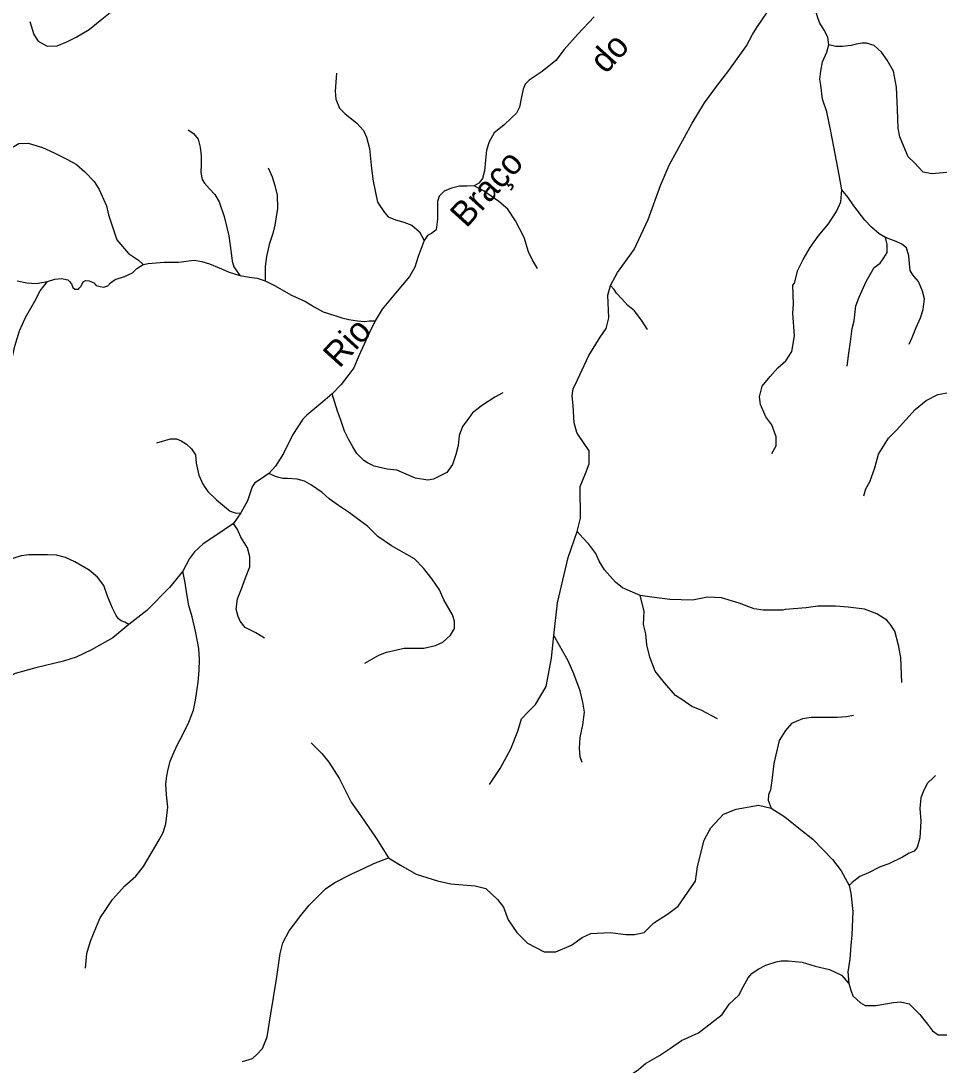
# Model space of a CAD drawing. Extents: x 436.3 to 500.4, y 8231 to 8286.4.
# Drawn here: x 466.93 to 474.29, y 8238.26 to 8246.62 of the extents above; entities that cross this region are included whole.
import ezdxf
from ezdxf.enums import TextEntityAlignment as Align

# ---------------------------------------------------------------- set-up
doc = ezdxf.new("R2010")
doc.units = 0
doc.header["$LTSCALE"] = 0.08
doc.linetypes.add('LONG_DASHED', pattern=[7.5, 6, -1.5])
doc.layers.add('61', color=7, linetype='Continuous')
doc.layers.add('9', color=7, linetype='LONG_DASHED', lineweight=25)

msp = doc.modelspace()

# ---------------------------------------------------------------- linework, layer by layer
at = {"layer": '9'}
for points in [[(467.005, 8246.619), (467.0356, 8246.5158), (467.07, 8246.4624), (467.1428, 8246.4206), (467.2232, 8246.4246), (467.2997, 8246.4554), (467.3763, 8246.4937), (467.4796, 8246.555), (467.5677, 8246.6279), (467.7016, 8246.7351), (467.7628, 8246.8079), (467.8088, 8246.8577), (467.8776, 8246.8999), (467.9656, 8246.9535), (468.0422, 8247.0339), (468.0843, 8247.1105), (468.1074, 8247.1845), (468.1226, 8247.303), (468.115, 8247.4025), (468.0614, 8247.5517), (468.0308, 8247.6435), (468.0039, 8247.7047)], [(471.6561, 8244.5046), (471.7121, 8244.6097), (471.845, 8244.7919), (471.958, 8245.0334), (472.0559, 8245.3065), (472.1259, 8245.4676), (472.3081, 8245.8037), (472.4074, 8245.9685), (472.5125, 8246.1086), (472.6036, 8246.2275), (472.7438, 8246.4237), (472.7929, 8246.5147), (472.828, 8246.5707), (472.9122, 8246.6969), (472.9684, 8246.7739), (473.0035, 8246.858), (473.0315, 8246.9701), (473.0528, 8247.1661)], [(473.404, 8246.4319), (473.3955, 8246.4933), (473.3672, 8246.5503), (473.3531, 8246.5713), (473.3322, 8246.6063), (473.3181, 8246.6412), (473.3042, 8246.6833), (473.2902, 8246.7603), (473.2833, 8246.8372), (473.2693, 8246.9073), (473.2273, 8246.9912), (473.1772, 8247.0397), (473.1165, 8247.0893), (473.0528, 8247.1661)], [(471.5237, 8246.6564), (471.3932, 8246.5179), (471.2831, 8246.3957), (471.2179, 8246.3061), (471.1067, 8246.2186), (471.0048, 8246.1493), (470.9722, 8246.1167), (470.9559, 8246.076), (470.9436, 8246.0149), (470.9274, 8245.9334), (470.903, 8245.8845), (470.8622, 8245.8478), (470.8002, 8245.7888), (470.7227, 8245.7277), (470.6821, 8245.6544), (470.6616, 8245.5892), (470.6536, 8245.5078), (470.6454, 8245.4222), (470.6292, 8245.361), (470.6007, 8245.3244), (470.564, 8245.304)], [(473.507, 8245.2707), (473.4858, 8245.3911), (473.4439, 8245.6151), (473.416, 8245.755), (473.3881, 8245.895), (473.3531, 8245.9963), (473.3392, 8246.1083), (473.3321, 8246.1573), (473.3393, 8246.2204), (473.3533, 8246.2974), (473.3884, 8246.3744), (473.404, 8246.4319)], [(474.3704, 8245.412), (474.3199, 8245.4073), (474.2283, 8245.398), (474.1595, 8245.4117), (474.0863, 8245.4894), (474.0405, 8245.5351), (474.0039, 8245.6174), (473.9719, 8245.6952), (473.9582, 8245.7638), (473.9537, 8245.9147), (473.9447, 8246.0932), (473.922, 8246.2212), (473.8714, 8246.309), (473.8256, 8246.3729), (473.7661, 8246.4278), (473.7064, 8246.446), (473.6698, 8246.4459), (473.624, 8246.4368), (473.5827, 8246.4276), (473.514, 8246.4183), (473.4589, 8246.4182), (473.404, 8246.4319)], [(469.4616, 8246.2048), (469.4496, 8246.0616), (469.4556, 8245.996), (469.4854, 8245.9244), (469.5272, 8245.8827), (469.6228, 8245.8051), (469.6766, 8245.7454), (469.7004, 8245.6917), (469.7243, 8245.6023), (469.7422, 8245.4411), (469.7542, 8245.3397), (469.7901, 8245.1726), (469.8438, 8245.089), (469.8737, 8245.0532), (469.9334, 8245.0292), (469.999, 8245.0112), (470.0648, 8244.9873), (470.1244, 8244.9335), (470.163, 8244.8648)], [(468.2731, 8245.7512), (468.3149, 8245.7219), (468.3525, 8245.6761), (468.3692, 8245.6134), (468.3776, 8245.5424), (468.3776, 8245.4757), (468.3734, 8245.4089), (468.386, 8245.3545), (468.4028, 8245.3253), (468.4445, 8245.2794), (468.4863, 8245.2334), (468.5199, 8245.175), (468.5617, 8245.058), (468.5994, 8244.9034), (468.6161, 8244.7654), (468.6245, 8244.6986), (468.6371, 8244.6525), (468.6871, 8244.5846)], [(466.6711, 8245.6228), (466.6978, 8245.6051), (466.7378, 8245.5786), (466.7511, 8245.5787), (466.8045, 8245.5832), (466.8223, 8245.5921), (466.8755, 8245.6188), (466.9155, 8245.6412), (466.9912, 8245.6457), (467.1067, 8245.6106), (467.2, 8245.5664), (467.3066, 8245.5134), (467.3777, 8245.4737), (467.4443, 8245.4162), (467.5199, 8245.3365), (467.5599, 8245.2745), (467.6177, 8245.1415), (467.6354, 8245.0704), (467.7021, 8244.8709), (467.7954, 8244.7601), (467.8754, 8244.7069), (467.911, 8244.6715)], [(468.913, 8245.4465), (468.9464, 8245.3754), (468.9673, 8245.3044), (468.9841, 8245.2291), (468.9883, 8245.1205), (468.9674, 8244.9868), (468.9507, 8244.9199), (468.9215, 8244.8322), (468.9006, 8244.736), (468.888, 8244.6565), (468.888, 8244.6189), (468.8903, 8244.5409)], [(470.564, 8245.304), (470.5069, 8245.3), (470.4458, 8245.3), (470.3805, 8245.2838), (470.3235, 8245.2594), (470.2827, 8245.2187), (470.2706, 8245.178), (470.2706, 8245.0353), (470.2584, 8244.9497), (470.2218, 8244.9212), (470.1892, 8244.905), (470.163, 8244.8648)], [(471.0714, 8244.6399), (471.0301, 8244.7071), (470.999, 8244.7743), (470.9628, 8244.888), (470.8956, 8245.0224), (470.8337, 8245.1153), (470.7613, 8245.1774), (470.6735, 8245.2394), (470.6425, 8245.26), (470.564, 8245.304)], [(472.9477, 8243.1575), (472.9826, 8243.2207), (472.9825, 8243.2909), (472.9474, 8243.3891), (472.8984, 8243.4523), (472.8562, 8243.5504), (472.8492, 8243.6136), (472.8701, 8243.6978), (472.9331, 8243.775), (472.996, 8243.8452), (473.059, 8243.9014), (473.1078, 8243.9754), (473.1288, 8244.1016), (473.1146, 8244.2839), (473.1216, 8244.354), (473.1145, 8244.5082), (473.1286, 8244.5222), (473.1565, 8244.6274), (473.1985, 8244.7115), (473.2546, 8244.8096), (473.3176, 8244.9008), (473.4017, 8244.9989), (473.4648, 8245.097), (473.4998, 8245.1741), (473.507, 8245.2707)], [(473.8591, 8244.888), (473.8073, 8244.919), (473.7452, 8244.9706), (473.6934, 8245.0275), (473.6054, 8245.1414), (473.5587, 8245.2086), (473.507, 8245.2707)], [(473.5499, 8243.8569), (473.5639, 8243.9621), (473.5778, 8244.0533), (473.5918, 8244.1585), (473.6057, 8244.2216), (473.6197, 8244.3408), (473.6477, 8244.4109), (473.7037, 8244.5371), (473.7668, 8244.6493), (473.8158, 8244.6844), (473.8439, 8244.7265), (473.8719, 8244.7686), (473.872, 8244.8315), (473.8591, 8244.888)], [(474.0479, 8244.0331), (474.0702, 8244.0889), (474.1037, 8244.1672), (474.1372, 8244.2454), (474.1595, 8244.3125), (474.1699, 8244.3962), (474.1544, 8244.4584), (474.1233, 8244.5361), (474.0871, 8244.5775), (474.0715, 8244.5982), (474.0559, 8244.624), (474.0508, 8244.681), (474.0456, 8244.7431), (474.0249, 8244.8053), (473.9887, 8244.8363), (473.9421, 8244.857), (473.8591, 8244.888)], [(470.163, 8244.8648), (470.1151, 8244.7368), (470.0884, 8244.6515), (470.0457, 8244.5768), (469.9338, 8244.4435), (469.8273, 8244.3156), (469.7708, 8244.2202)], [(467.911, 8244.6715), (467.9521, 8244.6793), (468.0791, 8244.6903), (468.1952, 8244.6903), (468.3205, 8244.708), (468.3822, 8244.6971), (468.4439, 8244.6791), (468.5201, 8244.6464), (468.6, 8244.6101), (468.6871, 8244.5846)], [(467.1461, 8244.5357), (467.2041, 8244.554), (467.2586, 8244.5614), (467.3094, 8244.5507), (467.3203, 8244.5398), (467.3384, 8244.5181), (467.3493, 8244.4891), (467.3639, 8244.4746), (467.3929, 8244.4747), (467.4002, 8244.4819), (467.4146, 8244.5001), (467.4328, 8244.5328), (467.4513, 8244.5443), (467.4803, 8244.5408), (467.5167, 8244.5264), (467.5348, 8244.5047), (467.5674, 8244.4974), (467.5966, 8244.4902), (467.6292, 8244.5012), (467.6509, 8244.5266), (467.6872, 8244.552), (467.7634, 8244.5775), (467.8265, 8244.6047), (467.8622, 8244.6403), (467.911, 8244.6715)], [(466.903, 8244.5423), (466.9792, 8244.5244), (467.0554, 8244.521), (467.1461, 8244.5357)], [(468.6871, 8244.5846), (468.7633, 8244.57), (468.8249, 8244.5628), (468.8903, 8244.5409)], [(468.8903, 8244.5409), (468.9629, 8244.5045), (469.1008, 8244.4281), (469.2133, 8244.3772), (469.2823, 8244.3335), (469.3549, 8244.2935), (469.4477, 8244.2643), (469.5022, 8244.246), (469.5603, 8244.2314), (469.6292, 8244.2204), (469.6873, 8244.2166), (469.7236, 8244.2203), (469.7708, 8244.2202)], [(466.5022, 8243.1071), (466.5447, 8243.1924), (466.6031, 8243.3045), (466.7467, 8243.5607), (466.7999, 8243.6513), (466.837, 8243.7792), (466.8582, 8243.8964), (466.8848, 8244.0189), (466.922, 8244.1414), (466.9699, 8244.2479), (467.0448, 8244.3776), (467.0873, 8244.4628), (467.1461, 8244.5357)], [(471.3892, 8242.533), (471.4138, 8242.6402), (471.4134, 8242.8931), (471.4553, 8242.9984), (471.4832, 8243.0756), (471.4831, 8243.181), (471.3983, 8243.3053), (471.3843, 8243.3264), (471.3632, 8243.4037), (471.356, 8243.544), (471.349, 8243.6212), (471.3559, 8243.6773), (471.3908, 8243.7474), (471.4816, 8243.9438), (471.5725, 8244.091), (471.6215, 8244.1611), (471.6424, 8244.2452), (471.6352, 8244.4275), (471.6561, 8244.5046)], [(471.9526, 8244.1517), (471.9077, 8244.2177), (471.8469, 8244.3023), (471.7941, 8244.3446), (471.7466, 8244.3974), (471.7044, 8244.4423), (471.6859, 8244.4714), (471.6561, 8244.5046)], [(469.7708, 8244.2202), (469.7259, 8244.1288), (469.6408, 8243.9419), (469.5982, 8243.8458), (469.5503, 8243.7817), (469.497, 8243.7124), (469.4258, 8243.635)], [(469.4258, 8243.635), (469.3512, 8243.571), (469.2232, 8243.4642), (469.1912, 8243.4322), (469.1114, 8243.3092), (469.0368, 8243.1595), (468.9728, 8243.0579), (468.9196, 8242.9991)], [(470.7926, 8243.6454), (470.7298, 8243.6094), (470.6311, 8243.5466), (470.5504, 8243.4837), (470.5056, 8243.4207), (470.4697, 8243.3758), (470.4429, 8243.3038), (470.434, 8243.2227), (470.4161, 8243.1507), (470.3893, 8243.0697), (470.3445, 8243.0067), (470.2368, 8242.9528), (470.1919, 8242.9439), (470.0946, 8242.9611), (470.0196, 8242.9925), (469.9445, 8243.024), (469.8664, 8243.0336), (469.7632, 8243.0557), (469.71, 8243.084), (469.6787, 8243.1028), (469.6224, 8243.1594), (469.5911, 8243.2127), (469.5566, 8243.2723), (469.5253, 8243.3382), (469.494, 8243.4323), (469.4689, 8243.4981), (469.4258, 8243.635)], [(473.6842, 8242.8196), (473.7, 8242.8752), (473.7316, 8242.9309), (473.7711, 8243.0423), (473.8027, 8243.1536), (473.8818, 8243.2808), (473.9452, 8243.3445), (474.0957, 8243.5115), (474.1829, 8243.5832), (474.278, 8243.631), (474.3652, 8243.647), (474.4445, 8243.6631), (474.5476, 8243.6552), (474.6825, 8243.592), (474.8095, 8243.5127), (474.9127, 8243.4731), (474.9762, 8243.4653), (475.1031, 8243.4892), (475.2301, 8243.5291), (475.3253, 8243.5769), (475.418, 8243.6362)], [(468.0221, 8243.2445), (468.1305, 8243.2771), (468.1792, 8243.2771), (468.2172, 8243.2609), (468.2605, 8243.2336), (468.2984, 8243.1956), (468.331, 8243.1467), (468.3365, 8243.0815), (468.3582, 8242.9837), (468.3908, 8242.913), (468.4288, 8242.8531), (468.4993, 8242.7878), (468.5644, 8242.7334), (468.6078, 8242.6953), (468.6566, 8242.679), (468.6941, 8242.6824)], [(468.9196, 8242.9991), (468.8502, 8242.951), (468.8077, 8242.9243), (468.7863, 8242.8921), (468.7486, 8242.7785), (468.6941, 8242.6824), (468.6349, 8242.5974)], [(469.6885, 8241.4784), (469.7984, 8241.5413), (469.8611, 8241.5675), (470.0025, 8241.5988), (470.1595, 8241.5985), (470.2537, 8241.6195), (470.3112, 8241.6456), (470.374, 8241.7034), (470.4054, 8241.7559), (470.4053, 8241.8137), (470.3896, 8241.8662), (470.3213, 8241.9872), (470.2845, 8242.0661), (470.2269, 8242.1503), (470.1587, 8242.2397), (470.0853, 8242.3133), (469.902, 8242.4188), (469.7919, 8242.4924), (469.7081, 8242.5766), (469.6504, 8242.6187), (469.565, 8242.6836), (469.4759, 8242.7416), (469.4025, 8242.7942), (469.3449, 8242.8468), (469.261, 8242.9047), (469.2034, 8242.9363), (469.1459, 8242.9521), (469.0673, 8242.9575), (469.0307, 8242.9576), (468.9888, 8242.9681), (468.9731, 8242.9734), (468.9196, 8242.9991)], [(468.6349, 8242.5974), (468.4874, 8242.4948), (468.3915, 8242.4359), (468.3222, 8242.3717), (468.284, 8242.316), (468.2307, 8242.2143)], [(468.8852, 8241.6781), (468.8147, 8241.7216), (468.7279, 8241.7652), (468.69, 8241.8142), (468.6736, 8241.8523), (468.6574, 8241.9121), (468.6681, 8241.9937), (468.7005, 8242.0752), (468.733, 8242.1623), (468.7653, 8242.2493), (468.7652, 8242.3308), (468.749, 8242.4016), (468.6947, 8242.4886), (468.6675, 8242.5485), (468.6349, 8242.5974)], [(471.2014, 8241.6994), (471.2311, 8241.9611), (471.3163, 8242.3241), (471.3892, 8242.533)], [(471.894, 8242.0206), (471.7508, 8242.0831), (471.6946, 8242.1269), (471.6074, 8242.2268), (471.5637, 8242.2955), (471.5388, 8242.358), (471.4826, 8242.433), (471.4327, 8242.4829), (471.3892, 8242.533)], [(467.0567, 8242.3465), (466.9967, 8242.3465), (466.9358, 8242.3392), (466.8757, 8242.3199), (466.8181, 8242.3), (466.7939, 8242.2858), (466.7715, 8242.2723), (466.7485, 8242.2603)], [(467.7973, 8241.7891), (467.7649, 8241.8083), (467.7349, 8241.8169), (467.7133, 8241.8341), (467.6961, 8241.86), (467.6659, 8241.9204), (467.6271, 8242.0154), (467.5969, 8242.1017), (467.5452, 8242.1664), (467.4807, 8242.2225), (467.3645, 8242.2915), (467.2913, 8242.3259), (467.2182, 8242.343), (467.1451, 8242.3472), (467.0677, 8242.3471), (467.0567, 8242.3465)], [(467.4504, 8239.0358), (467.4602, 8239.1537), (467.4896, 8239.252), (467.5386, 8239.3699), (467.5681, 8239.4386), (467.6073, 8239.4976), (467.6662, 8239.586), (467.7642, 8239.6941), (467.8525, 8239.7727), (467.9158, 8239.8499), (468.04, 8240.0644), (468.0719, 8240.1224), (468.095, 8240.192), (468.1094, 8240.3253), (468.0978, 8240.424), (468.0948, 8240.511), (468.1006, 8240.5732), (468.1092, 8240.6167), (468.1294, 8240.6922), (468.1525, 8240.7502), (468.1842, 8240.8227), (468.2334, 8240.9126), (468.2767, 8241.0054), (468.3141, 8241.1012), (468.3314, 8241.1825), (468.3517, 8241.3263), (468.3603, 8241.4192), (468.3631, 8241.5091), (468.3572, 8241.5963), (468.331, 8241.7356), (468.3047, 8241.8504), (468.2787, 8241.9404), (468.2583, 8242.0507), (468.2496, 8242.1233), (468.2307, 8242.2143)], [(468.2307, 8242.2143), (468.1242, 8242.0857), (467.9413, 8241.9017), (467.7973, 8241.7891)], [(472.5123, 8241.0329), (472.3815, 8241.1015), (472.3068, 8241.1326), (472.2259, 8241.1887), (472.176, 8241.22), (472.0887, 8241.3198), (472.014, 8241.4135), (471.9702, 8241.5259), (471.9451, 8241.6259), (471.9388, 8241.7133), (471.92, 8241.7883), (471.926, 8241.8945), (471.894, 8242.0206)], [(473.9882, 8241.3236), (473.9817, 8241.5233), (473.9628, 8241.6232), (473.9316, 8241.7355), (473.8941, 8241.7917), (473.8692, 8241.8228), (473.7882, 8241.8726), (473.6885, 8241.9099), (473.5577, 8241.9284), (473.4581, 8241.9345), (473.3149, 8241.9342), (473.2216, 8241.9216), (473.0536, 8241.9088), (473.0349, 8241.9025), (472.8793, 8241.9023), (472.8047, 8241.9147), (472.6864, 8241.9582), (472.5432, 8242.0018), (472.4311, 8242.008), (472.3129, 8241.9828), (472.1305, 8241.9895), (471.9873, 8242.0082), (471.894, 8242.0206)], [(467.7973, 8241.7891), (467.6692, 8241.6819), (467.4986, 8241.5854), (467.3759, 8241.5264), (467.2745, 8241.4941), (467.0537, 8241.4398), (466.8882, 8241.3968), (466.7388, 8241.327), (466.5733, 8241.2465), (466.488, 8241.1767), (466.3972, 8241.0909), (466.3332, 8241.0641), (466.2851, 8241.064), (466.205, 8241.0907), (466.1196, 8241.1067), (466.0342, 8241.1066), (465.9808, 8241.0743)], [(470.6857, 8240.5062), (470.7709, 8240.6344), (470.8561, 8240.7914), (470.9128, 8240.9339), (470.9412, 8241.0338), (470.9981, 8241.0909), (471.0549, 8241.1479), (471.0975, 8241.2192), (471.14, 8241.2906), (471.1824, 8241.519), (471.2014, 8241.6994)], [(471.4284, 8240.6826), (471.4133, 8240.7279), (471.4082, 8240.7984), (471.4131, 8240.8839), (471.433, 8240.9845), (471.448, 8241.0852), (471.4328, 8241.1658), (471.4126, 8241.2563), (471.3623, 8241.3923), (471.317, 8241.498), (471.2718, 8241.5786), (471.2467, 8241.6189), (471.2014, 8241.6994)], [(473.6024, 8241.0601), (473.5449, 8241.0494), (473.4714, 8241.044), (473.3718, 8241.0437), (473.2618, 8241.0435), (473.1938, 8241.0328), (473.1413, 8241.0117), (473.1047, 8240.9959), (473.0576, 8240.938), (473.0053, 8240.8591), (472.9637, 8240.6751), (472.948, 8240.5385), (472.9376, 8240.4649), (472.9219, 8240.4228), (472.9168, 8240.3808), (472.9428, 8240.3174)], [(469.2584, 8240.8411), (469.3439, 8240.7553), (469.3984, 8240.6851), (469.4839, 8240.5527), (469.5772, 8240.3656), (469.655, 8240.2566), (469.7793, 8240.0774), (469.8772, 8239.9185)], [(474.2577, 8240.5782), (474.2421, 8240.5627), (474.1955, 8240.5158), (474.1645, 8240.4613), (474.1412, 8240.3991), (474.1336, 8240.3135), (474.1414, 8240.2125), (474.1338, 8240.0803), (474.1104, 8240.0026), (474.0872, 8239.9714), (474.0484, 8239.9558), (473.994, 8239.9245), (473.8852, 8239.8699), (473.8153, 8239.8465), (473.7221, 8239.7996), (473.6523, 8239.7684), (473.5901, 8239.7216), (473.5669, 8239.6982)], [(469.8772, 8239.9185), (469.9736, 8239.8592), (470.0979, 8239.7891), (470.2688, 8239.7344), (470.3775, 8239.711), (470.5717, 8239.6952), (470.6572, 8239.6719), (470.7504, 8239.5862), (470.797, 8239.524), (470.8359, 8239.4229), (470.9057, 8239.3219), (470.9911, 8239.2364), (471.1232, 8239.1665), (471.218, 8239.165), (471.3422, 8239.2193), (471.4276, 8239.2814), (471.4975, 8239.3125), (471.6528, 8239.3202), (471.7771, 8239.3048), (471.8469, 8239.3049), (471.9245, 8239.3204), (472.0023, 8239.3982), (472.1109, 8239.4681), (472.1963, 8239.5304), (472.305, 8239.6859), (472.336, 8239.7325), (472.3516, 8239.8491), (472.4057, 8240.0591), (472.46, 8240.1603), (472.5609, 8240.2694), (472.6618, 8240.3086), (472.8402, 8240.3401), (472.9428, 8240.3174)], [(472.9428, 8240.3174), (473.0515, 8240.2478), (473.1758, 8240.1469), (473.2767, 8240.0695), (473.4321, 8239.9066), (473.502, 8239.8136), (473.5669, 8239.6982)], [(468.7083, 8238.2885), (468.7888, 8238.3104), (468.8253, 8238.3469), (468.8691, 8238.3908), (468.9057, 8238.4858), (468.935, 8238.6685), (468.9568, 8238.8001), (468.9788, 8238.9463), (469.0081, 8239.1511), (469.0299, 8239.2388), (469.0811, 8239.3339), (469.176, 8239.4582), (469.2418, 8239.5386), (469.3733, 8239.6702), (469.4463, 8239.7214), (469.5777, 8239.7871), (469.6873, 8239.8382), (469.7603, 8239.8748), (469.8772, 8239.9185)], [(473.5669, 8239.6982), (473.5797, 8239.6351), (473.5953, 8239.4876), (473.5875, 8239.3013), (473.5797, 8239.216), (473.5719, 8239.1072), (473.5564, 8239.0064), (473.5641, 8238.9133)], [(471.7648, 8238.1469), (471.8807, 8238.2242), (471.9347, 8238.2705), (472.0467, 8238.3362), (472.1355, 8238.3942), (472.2242, 8238.4559), (472.3593, 8238.5178), (472.4674, 8238.599), (472.5485, 8238.6647), (472.6064, 8238.7458), (472.6837, 8238.8192), (472.7184, 8238.8848), (472.7571, 8238.9582), (472.7879, 8238.9929), (472.8381, 8239.0278), (472.8998, 8239.0588), (472.9809, 8239.086), (473.0233, 8239.0938), (473.0773, 8239.094), (473.1892, 8239.0827), (473.2935, 8239.0521), (473.4092, 8239.0254), (473.5057, 8238.9794), (473.5641, 8238.9133)], [(473.5641, 8238.9133), (473.5796, 8238.8591), (473.5951, 8238.8125), (473.6573, 8238.7584), (473.6961, 8238.7353), (473.7815, 8238.7355), (473.9212, 8238.7591), (473.9777, 8238.7641), (474.0476, 8238.7487), (474.0786, 8238.7178), (474.133, 8238.6636), (474.1951, 8238.5863), (474.2339, 8238.5321), (474.2805, 8238.5012), (474.3815, 8238.5014)]]:
    msp.add_lwpolyline(points, dxfattribs=at)

# ---------------------------------------------------------------- texts
at = {"layer": '61'}
msp.add_text('Rio               Braço             do            Sul', height=0.2, rotation=47.862, dxfattribs=at).set_placement((471.0794, 8245.5977), align=Align.CENTER)

doc.saveas('drawing.dxf')
